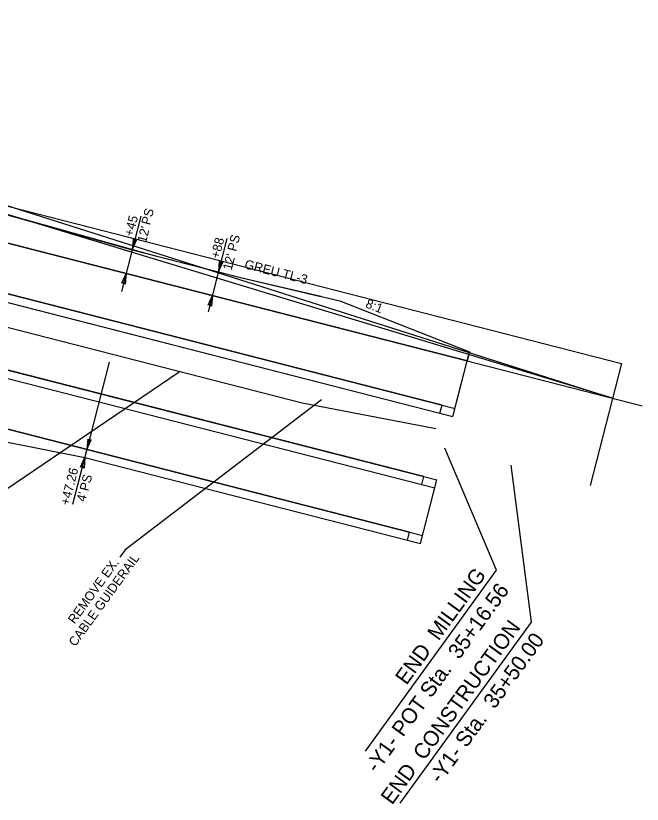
# Model space of a CAD drawing. Extents: x 1183930 to 1185370, y 573068 to 574871.
# Drawn here: x 1184757.1 to 1185063.3, y 573790.3 to 574175.3 of the extents above; entities that cross this region are included whole.
import ezdxf

# ---------------------------------------------------------------- set-up
doc = ezdxf.new("R2010")
doc.units = 0
for name, color, linetype in [('E_NCDOT_Vertical_Profile_Ground_Line', 7, 'Continuous'), ('P_NCDOT_Horizontal_Alignment', 7, 'Continuous'), ('P_NCDOT_Horizontal_Alignment_Tick_Large', 7, 'Continuous'), ('P_NCDOT_Horizontal_Alignment_Tick_Small', 7, 'Continuous'), ('P_NCDOT_Vertical_Profile_Ditch_Grade_Left', 7, 'Continuous'), ('P_SMU_Deck', 7, 'Continuous'), ('PC_OBJECT', 7, 'Continuous'), ('PC_PADFOOTING', 7, 'Continuous'), ('PS_HATCH', 7, 'Continuous')]:
    doc.layers.add(name, color=color, linetype=linetype)

msp = doc.modelspace()

# ---------------------------------------------------------------- linework, layer by layer
for points in [[(1184814.42, 574066.15), (1184814.01, 574061.03), (1184816.14, 574065.74), (1184815.11, 574065.33)], [(1184856.57, 574055.36), (1184856.16, 574050.24), (1184858.3, 574054.94), (1184857.26, 574054.54)], [(1184808.93, 574044.71), (1184811.03, 574049.4), (1184810.64, 574044.25), (1184809.93, 574045.1)], [(1184851.08, 574033.92), (1184853.18, 574038.61), (1184852.79, 574033.46), (1184852.08, 574034.31)], [(1184792.3, 573968.58), (1184791.89, 573963.46), (1184794.03, 573968.17), (1184793, 573967.77)], [(1184788.8, 573954.9), (1184790.9, 573959.59), (1184790.51, 573954.43), (1184789.8, 573955.28)]]:
    msp.add_lwpolyline(points, close=True)
at = {"layer": 'E_NCDOT_Vertical_Profile_Ground_Line'}
for p, q in [((1184595.86, 574075.58), (1184964.43, 573981.23)), ((1184595.86, 574075.58), (1184964.43, 573981.23)), ((1184595.86, 574075.58), (1184970.78, 573979.6)), ((1184814.01, 574061.03), (1184856.16, 574050.24)), ((1184814.01, 574061.03), (1184856.16, 574050.24)), ((1184587.92, 574044.58), (1184956.49, 573950.23)), ((1184587.92, 574044.58), (1184956.49, 573950.23)), ((1184587.92, 574044.58), (1184962.85, 573948.6)), ((1184915.55, 574036.06), (1184978.86, 574011.15)), ((1184594.42, 573998.53), (1184790.9, 573959.59)), ((1184790.9, 573959.59), (1184948.56, 573919.23)), ((1184790.9, 573959.59), (1184954.91, 573917.6))]:
    msp.add_line(p, q, dxfattribs=at)
for points in [[(1184669.44, 574101.14), (1184680.13, 574098.4), (1184814.01, 574061.03)], [(1184856.16, 574050.24), (1184866.86, 574047.5), (1184906.15, 574038.29)], [(1184856.16, 574050.24), (1184866.86, 574047.5), (1184906.14, 574038.27)], [(1184856.16, 574050.24), (1184866.86, 574047.5), (1184915.55, 574036.06)], [(1184856.16, 574050.24), (1184866.86, 574047.5), (1184904.8, 574038.61)]]:
    msp.add_lwpolyline(points, dxfattribs=at)
at = {"layer": 'P_NCDOT_Horizontal_Alignment'}
for p, q in [((1184143.08, 574220.4), (1184971.37, 574008.35)), ((1184143.08, 574220.4), (1184977.73, 574006.73)), ((1184137.13, 574197.15), (1184965.42, 573985.1)), ((1184137.13, 574197.15), (1184971.78, 573983.48)), ((1184127.21, 574158.4), (1184955.5, 573946.35)), ((1184127.21, 574158.4), (1184961.86, 573944.73)), ((1184121.26, 574135.15), (1184949.55, 573923.1)), ((1184121.26, 574135.15), (1184955.9, 573921.48)), ((1184649.48, 574115.48), (1185048.75, 573988.56)), ((1184647.89, 574109.23), (1185053.08, 574005.5)), ((1185048.75, 573988.56), (1184665.2, 574104.8)), ((1184970.78, 573979.6), (1184978.86, 574011.15)), ((1184970.92, 573980.15), (1184978.86, 574011.15)), ((1184971.37, 574008.35), (1185063.28, 573984.83)), ((1185053.08, 574005.5), (1185037.83, 573945.92)), ((1184954.91, 573917.6), (1184962.85, 573948.6))]:
    msp.add_line(p, q, dxfattribs=at)
at = {"layer": 'P_NCDOT_Horizontal_Alignment_Tick_Large'}
for p, q in [((1184680.13, 574098.4), (1184824.7, 574058.29)), ((1184824.7, 574058.29), (1184866.86, 574047.5))]:
    msp.add_line(p, q, dxfattribs=at)
at = {"layer": 'P_NCDOT_Horizontal_Alignment_Tick_Small'}
msp.add_line((1184866.86, 574047.5), (1184904.87, 574038.57), dxfattribs=at)
at = {"layer": 'P_NCDOT_Vertical_Profile_Ditch_Grade_Left'}
msp.add_lwpolyline([(1184962.48, 573973.62), (1184897.15, 573986.07), (1184692.42, 574038.48)], dxfattribs=at)
at = {"layer": 'P_SMU_Deck'}
msp.add_line((1184802.81, 574006.09), (1184791.89, 573963.46), dxfattribs=at)
at = {"layer": 'PC_OBJECT'}
for p, q in [((1184977.73, 574006.73), (1184596.71, 574104.27)), ((1184965.42, 573985.1), (1184581.58, 574083.37)), ((1184595.86, 574075.58), (1184964.43, 573981.23)), ((1184814.01, 574061.03), (1184856.16, 574050.24)), ((1184556.37, 574048.53), (1184955.5, 573946.35)), ((1184956.49, 573950.23), (1184587.92, 574044.58)), ((1184915.55, 574036.06), (1184978.86, 574011.15)), ((1184949.55, 573923.1), (1184541.24, 574027.63)), ((1184978.86, 574011.15), (1184977.73, 574006.73)), ((1184594.42, 573998.53), (1184790.9, 573959.59)), ((1184964.43, 573981.23), (1184965.42, 573985.1)), ((1184790.9, 573959.59), (1184948.56, 573919.23)), ((1184955.5, 573946.35), (1184956.49, 573950.23)), ((1184948.56, 573919.23), (1184949.55, 573923.1))]:
    msp.add_line(p, q, dxfattribs=at)
for points in [[(1184669.44, 574101.14), (1184680.13, 574098.4), (1184814.01, 574061.03)], [(1184856.16, 574050.24), (1184866.86, 574047.5), (1184915.55, 574036.06)]]:
    msp.add_lwpolyline(points, dxfattribs=at)
at = {"layer": 'PC_PADFOOTING'}
for p, q in [((1184818.18, 574077.35), (1184808.77, 574040.57)), ((1184860.34, 574066.55), (1184851.18, 574030.79)), ((1184742.42, 573937.4), (1184836.91, 574001.49)), ((1184811.17, 573915.11), (1184906.55, 573987.94)), ((1184785.05, 573936.73), (1184793.43, 573969.46))]:
    msp.add_line(p, q, dxfattribs=at)
msp.add_lwpolyline([(1184808.06, 573910.83), (1184811.17, 573915.11)], dxfattribs=at)
at = {"layer": 'PS_HATCH'}
for p, q in [((1184594.42, 573998.53), (1184790.9, 573959.59)), ((1184992.13, 573904.61), (1184966.82, 573964.1)), ((1185009.21, 573879.14), (1184999.29, 573955.79)), ((1184927.97, 573816.18), (1184992.13, 573904.61)), ((1184945.05, 573790.71), (1185009.21, 573879.14))]:
    msp.add_line(p, q, dxfattribs=at)

# ---------------------------------------------------------------- texts
at = {"layer": 'PC_PADFOOTING'}
for s, rotation, p in [('PS', 75.6405, (1184822.71, 574072.82)), ('+45', 75.6405, (1184814.39, 574067.21)), ("12'", 75.6405, (1184820.74, 574064.18)), ('+88', 75.6405, (1184856.55, 574056.43)), ('PS', 75.6405, (1184864.82, 574059.93)), ("12'", 75.6405, (1184862.56, 574050.71)), ('8:1', 338.5714, (1184927.68, 574033)), ('+47.26', 75.6405, (1184783.14, 573935.91)), ('PS', 75.6405, (1184792.56, 573942.87)), ("4'", 75.6405, (1184791.06, 573937.66)), ('CABLE GUIDERAIL', 54.0376, (1184786.21, 573866.93)), ('REMOVE EX.', 54.0376, (1184785.87, 573877.96))]:
    msp.add_text(s, height=4.5, rotation=rotation, dxfattribs=at).set_placement(p)
at = {"layer": 'PS_HATCH'}
for s, height, rotation, p in [('GREU TL-3', 4.5, 345.6405, (1184868.59, 574051.99)), ('END  MILLING', 7.5, 54.0376, (1184948.06, 573848.06)), ('-Y1- POT Sta.  35+16.56', 7.5, 54.0376, (1184933.57, 573805.12)), ('END  CONSTRUCTION', 7.5, 54.0376, (1184941, 573789.59)), ('-Y1- Sta.  35+50.00', 7.5, 54.0376, (1184964.58, 573799.84))]:
    msp.add_text(s, height=height, rotation=rotation, dxfattribs=at).set_placement(p)

doc.saveas('drawing.dxf')
